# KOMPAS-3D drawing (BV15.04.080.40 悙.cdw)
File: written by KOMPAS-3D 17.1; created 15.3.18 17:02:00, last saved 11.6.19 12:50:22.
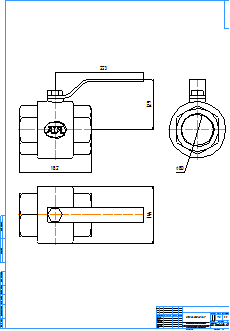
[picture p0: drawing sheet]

Sheet 1: A1, portrait

Title block, sheet 1: name: BV15.04.080.40 Р/Р; material: Внимание! Данный продукт является объектом авторского права ООО «Торговый Дом АДЛ». / Запрещается изменение, копирование, распространение / (в том числе путем копирования на другие сайты и ресурсы в Интернете) / или любое иное использование информации и объектов без предварительного / согласия правообладателя (ООО «Торговый Дом АДЛ»).; mass: 7,8; sheets: 1; organisation: ООО "Торговый дом АДЛ"; sheet format: A1; stored path: \\adlc.lan\data\АДЛ_ПКД\3D-модели\ADL production\Краны шаровые серии BV\BV15\KOMPAS 2D\BV15.04.080.40 РР.cdw

Views: Вид 1, Проекционный вид 2, Проекционный вид 3
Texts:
  kka
  adl
Dimensions and other numbers on the sheet: 182; 223; 129; 80; 144; 1:1; 1; 7,8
